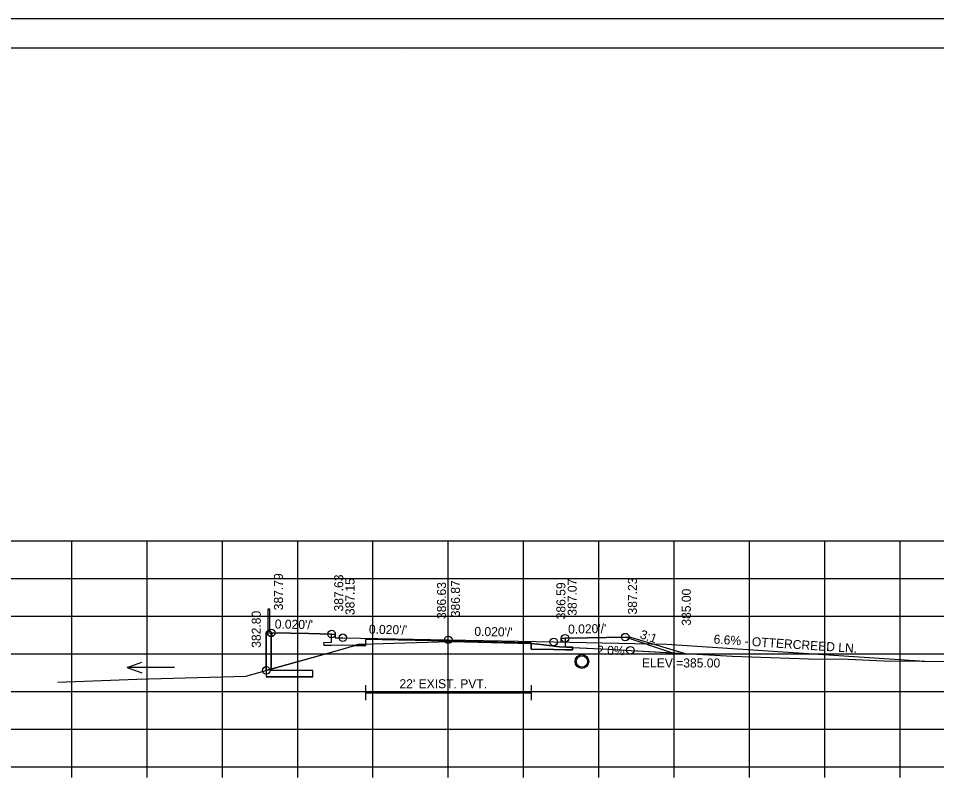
# Model space of a CAD drawing. Extents: x -37291014 to -37290680, y -936053 to -933067.
# Drawn here: x -37290900.2 to -37290778.3, y -933594.7 to -933493.3 of the extents above; entities that cross this region are included whole.
import ezdxf

# ---------------------------------------------------------------- set-up
doc = ezdxf.new("R2010")
doc.units = 0
for name, color, linetype in [('Default', 7, 'Continuous'), ('R_Alt Surface', 7, 'Continuous'), ('R_Axis', 7, 'Continuous'), ('R_Border', 7, 'Continuous'), ('R_Contours', 7, 'Continuous'), ('R_Drive', 7, 'Continuous'), ('R_Exist Surface', 7, 'Continuous'), ('R_Fin Surface', 7, 'Continuous'), ('R_Grid', 7, 'Continuous'), ('R_No Plot', 7, 'Continuous'), ('R_Water', 7, 'Continuous'), ('R_Water Annot', 7, 'Continuous'), ('R_Xsect Elev', 7, 'Continuous'), ('R_Xsect Slope', 7, 'Continuous')]:
    doc.layers.add(name, color=color, linetype=linetype)

msp = doc.modelspace()

# ---------------------------------------------------------------- linework, layer by layer
at = {"layer": 'Default'}
for p, q in [((-37290867.02, -933574.63), (-37290867.02, -933571.63)), ((-37290867.02, -933571.63), (-37290866.85, -933571.63)), ((-37290866.85, -933571.63), (-37290866.85, -933574.63)), ((-37290867.21, -933574.65), (-37290867.27, -933574.72)), ((-37290867.27, -933574.72), (-37290867.27, -933580.64)), ((-37290866.66, -933574.63), (-37290867.21, -933574.63)), ((-37290867.21, -933574.63), (-37290867.21, -933574.65)), ((-37290866.66, -933574.65), (-37290867.21, -933574.65)), ((-37290866.66, -933574.65), (-37290866.66, -933574.63)), ((-37290866.6, -933574.72), (-37290866.66, -933574.65)), ((-37290866.6, -933579.8), (-37290866.6, -933574.72)), ((-37290861.1, -933579.8), (-37290866.6, -933579.8)), ((-37290861.1, -933580.64), (-37290861.1, -933579.8)), ((-37290861.1, -933580.64), (-37290867.27, -933580.64))]:
    msp.add_line(p, q, dxfattribs=at)
msp.add_lwpolyline([(-37290866.52, -933575.32), (-37290866.6, -933575.32), (-37290866.6, -933574.82), (-37290866.52, -933574.82), (-37290866.52, -933575.32)], dxfattribs=at)
at = {"layer": 'R_Alt Surface'}
for points in [[(-37290827.6, -933575.54), (-37290827.6, -933576.63), (-37290826.59, -933576.65), (-37290826.6, -933577.07), (-37290827.6, -933577.05), (-37290829.1, -933577.02), (-37290832.1, -933576.96), (-37290832.1, -933576.13), (-37290843.1, -933575.91), (-37290854.1, -933575.69), (-37290854.1, -933576.52), (-37290857.1, -933576.46), (-37290858.6, -933576.49), (-37290859.6, -933576.51), (-37290859.61, -933576.09), (-37290858.6, -933576.07), (-37290858.6, -933574.98)], [(-37290854.1, -933581.77), (-37290854.1, -933583.77)], [(-37290854.1, -933582.77), (-37290832.1, -933582.77)], [(-37290832.1, -933581.77), (-37290832.1, -933583.77)]]:
    msp.add_lwpolyline(points, dxfattribs=at)
at = {"layer": 'R_Axis'}
for p, q in [((-37290993.1, -933592.61), (-37290693.1, -933592.61)), ((-37290893.1, -933594.01), (-37290893.1, -933592.61)), ((-37290883.1, -933594.01), (-37290883.1, -933592.61)), ((-37290873.1, -933594.01), (-37290873.1, -933592.61)), ((-37290863.1, -933594.01), (-37290863.1, -933592.61)), ((-37290853.1, -933594.01), (-37290853.1, -933592.61)), ((-37290843.1, -933594.01), (-37290843.1, -933592.61)), ((-37290833.1, -933594.01), (-37290833.1, -933592.61)), ((-37290823.1, -933594.01), (-37290823.1, -933592.61)), ((-37290813.1, -933594.01), (-37290813.1, -933592.61)), ((-37290803.1, -933594.01), (-37290803.1, -933592.61)), ((-37290793.1, -933594.01), (-37290793.1, -933592.61)), ((-37290783.1, -933594.01), (-37290783.1, -933592.61))]:
    msp.add_line(p, q, dxfattribs=at)
at = {"layer": 'R_Border'}
for p, q in [((-37291001.1, -933497.15), (-37290684.92, -933497.15)), ((-37290848.58, -933497.41), (-37290848.58, -933497.41)), ((-37290848.58, -933497.41), (-37290848.58, -933497.41))]:
    msp.add_line(p, q, dxfattribs=at)
at = {"layer": 'R_Contours'}
for p, q in [((-37290866.6, -933575.32), (-37290866.6, -933579.61)), ((-37290813.4, -933577.45), (-37290819.6, -933575.38)), ((-37290855.55, -933576.49), (-37290854.1, -933576.52)), ((-37290854.1, -933576.52), (-37290854.1, -933576.32)), ((-37290832.1, -933576.24), (-37290832.1, -933576.13)), ((-37290832.1, -933576.24), (-37290832.1, -933576.96)), ((-37290826.59, -933576.75), (-37290821.9, -933576.96)), ((-37290821.9, -933576.96), (-37290813.4, -933577.45)), ((-37290866.6, -933579.61), (-37290867.27, -933579.8)), ((-37290866.6, -933579.8), (-37290866.6, -933579.61)), ((-37290861.1, -933579.8), (-37290866.6, -933579.8)), ((-37290861.1, -933580.64), (-37290861.1, -933579.8)), ((-37290867.27, -933580.64), (-37290861.1, -933580.64))]:
    msp.add_line(p, q, dxfattribs=at)
for points in [[(-37290866.52, -933574.82), (-37290866.52, -933575.32), (-37290866.6, -933575.32)], [(-37290858.6, -933574.98), (-37290861.6, -933574.92), (-37290866.52, -933574.82)], [(-37290855.55, -933576.49), (-37290857.1, -933576.46), (-37290858.6, -933576.49), (-37290859.6, -933576.51), (-37290859.61, -933576.09), (-37290858.6, -933576.07), (-37290858.6, -933574.98)], [(-37290819.6, -933575.38), (-37290824.6, -933575.48), (-37290827.6, -933575.54)], [(-37290827.6, -933575.54), (-37290827.6, -933576.63), (-37290826.59, -933576.65), (-37290826.59, -933576.75)], [(-37290866.6, -933579.61), (-37290857.83, -933577.14), (-37290855.55, -933576.49)], [(-37290854.1, -933576.32), (-37290855.07, -933576.35), (-37290855.55, -933576.49)], [(-37290832.1, -933576.13), (-37290843.1, -933575.91), (-37290854.1, -933575.69), (-37290854.1, -933576.32)], [(-37290854.1, -933576.32), (-37290853.19, -933576.29), (-37290842.94, -933575.97), (-37290840.91, -933576.02), (-37290832.1, -933576.24)], [(-37290826.59, -933576.75), (-37290828.34, -933576.67), (-37290830.42, -933576.41), (-37290832.1, -933576.24)], [(-37290832.1, -933576.24), (-37290832.1, -933576.24)], [(-37290832.1, -933576.96), (-37290829.1, -933577.02), (-37290827.6, -933577.05), (-37290826.6, -933577.07), (-37290826.59, -933576.75)], [(-37290867.27, -933579.8), (-37290867.27, -933579.8), (-37290867.27, -933580.64)]]:
    msp.add_lwpolyline(points, dxfattribs=at)
at = {"layer": 'R_Drive'}
for p, q in [((-37290829.1, -933576.02), (-37290814.1, -933576.32)), ((-37290814.1, -933576.32), (-37290779.84, -933578.58))]:
    msp.add_line(p, q, dxfattribs=at)
at = {"layer": 'R_Exist Surface'}
msp.add_lwpolyline([(-37290894.96, -933581.34), (-37290884.45, -933580.97), (-37290869.97, -933580.56), (-37290857.83, -933577.14), (-37290855.07, -933576.35), (-37290853.19, -933576.29), (-37290842.94, -933575.97), (-37290840.91, -933576.02), (-37290832.1, -933576.24), (-37290830.42, -933576.41), (-37290828.34, -933576.67), (-37290821.9, -933576.96), (-37290805.37, -933577.91), (-37290795.28, -933578.26), (-37290790, -933578.32), (-37290785.24, -933578.53), (-37290770.21, -933578.67)], dxfattribs=at)
at = {"layer": 'R_Fin Surface'}
msp.add_lwpolyline([(-37290867.27, -933579.8), (-37290867.27, -933574.82), (-37290866.6, -933574.82), (-37290861.6, -933574.92), (-37290858.6, -933574.98), (-37290858.1, -933574.98), (-37290858.1, -933575.48), (-37290857.1, -933575.46), (-37290843.1, -933575.74), (-37290829.1, -933576.02), (-37290828.1, -933576.04), (-37290828.1, -933575.54), (-37290827.6, -933575.54), (-37290824.6, -933575.48), (-37290819.6, -933575.38), (-37290818.93, -933575.38), (-37290811.51, -933577.61)], dxfattribs=at)
at = {"layer": 'R_Grid'}
for p, q in [((-37290993.1, -933562.61), (-37290693.1, -933562.61)), ((-37290893.1, -933592.61), (-37290893.1, -933562.61)), ((-37290883.1, -933592.61), (-37290883.1, -933562.61)), ((-37290873.1, -933592.61), (-37290873.1, -933562.61)), ((-37290863.1, -933592.61), (-37290863.1, -933562.61)), ((-37290853.1, -933592.61), (-37290853.1, -933562.61)), ((-37290843.1, -933592.61), (-37290843.1, -933562.61)), ((-37290833.1, -933592.61), (-37290833.1, -933562.61)), ((-37290823.1, -933592.61), (-37290823.1, -933562.61)), ((-37290813.1, -933592.61), (-37290813.1, -933562.61)), ((-37290803.1, -933592.61), (-37290803.1, -933562.61)), ((-37290793.1, -933592.61), (-37290793.1, -933562.61)), ((-37290783.1, -933592.61), (-37290783.1, -933562.61)), ((-37290993.1, -933567.61), (-37290693.1, -933567.61)), ((-37290993.1, -933572.61), (-37290693.1, -933572.61)), ((-37290993.1, -933577.61), (-37290693.1, -933577.61)), ((-37290993.1, -933582.61), (-37290693.1, -933582.61)), ((-37290993.1, -933587.61), (-37290693.1, -933587.61)), ((-37290993.1, -933592.61), (-37290693.1, -933592.61))]:
    msp.add_line(p, q, dxfattribs=at)
at = {"layer": 'R_No Plot'}
msp.add_line((-37291013.5, -933493.25), (-37290680.17, -933493.25), dxfattribs=at)
for points in [[(-37291013.51, -933493.25), (-37290680.17, -933493.25), (-37290680.17, -933706.59), (-37291013.51, -933706.59)], [(-37290767.18, -933497.15), (-37290747.56, -933497.15), (-37290747.56, -933507.03), (-37290731.45, -933507.03), (-37290708.25, -933507.03), (-37290708.25, -933531.36), (-37290684.92, -933531.36), (-37290684.92, -933702.61), (-37291001.1, -933702.61), (-37291001.1, -933497.15)]]:
    msp.add_lwpolyline(points, close=True, dxfattribs=at)
for centre, radius in [((-37290866.6, -933574.82), 0.5), ((-37290858.6, -933574.98), 0.5), ((-37290857.1, -933575.46), 0.5), ((-37290843.1, -933575.74), 0.5), ((-37290829.1, -933576.02), 0.5), ((-37290827.6, -933575.54), 0.5), ((-37290819.6, -933575.38), 0.5), ((-37290818.93, -933577.13), 0.5), ((-37290825.36, -933578.62), 0.917), ((-37290867.27, -933579.8), 0.5)]:
    msp.add_circle(centre, radius, dxfattribs=at)
at = {"layer": 'R_Water'}
msp.add_circle((-37290825.36, -933578.62), 0.75, dxfattribs=at)
at = {"layer": 'R_Water Annot'}
for p, q in [((-37290885.72, -933579.42), (-37290883.8, -933578.72)), ((-37290879.44, -933579.42), (-37290885.72, -933579.42)), ((-37290885.72, -933579.42), (-37290883.8, -933580.12))]:
    msp.add_line(p, q, dxfattribs=at)
at = {"layer": 'R_Xsect Elev'}
msp.add_line((-37290843.1, -933575.98), (-37290843.1, -933565.98), dxfattribs=at)

# ---------------------------------------------------------------- texts
at = {"layer": 'R_Water'}
msp.add_text("22' EXIST. PVT.", height=1.2, dxfattribs=at).set_placement((-37290849.58, -933582.17))
at = {"layer": 'R_Xsect Elev'}
for s, rotation, p in [('387.79', 90, (-37290865.05, -933571.82)), ('387.63', 90, (-37290857.05, -933571.98)), ('387.15', 90, (-37290855.55, -933572.46)), ('386.63', 90, (-37290843.4, -933572.98)), ('386.87', 90, (-37290841.55, -933572.74)), ('386.59', 90, (-37290827.55, -933573.02)), ('387.07', 90, (-37290826.05, -933572.54)), ('387.23', 90, (-37290818.05, -933572.38)), ('385.00', 90, (-37290810.9, -933573.86)), ('382.80', 90, (-37290868, -933576.8)), ('6.6% - OTTERCREED LN.', 356.224, (-37290807.9, -933576.23)), ('2.0%', 358.8542, (-37290823.35, -933577.71))]:
    msp.add_text(s, height=1.2, rotation=rotation, dxfattribs=at).set_placement(p)
msp.add_text('ELEV.=385.00', height=1.2, dxfattribs=at).set_placement((-37290817.39, -933579.41))
at = {"layer": 'R_Xsect Slope'}
for s, rotation, p in [("0.020'/'", 358.8542, (-37290866.15, -933574.23)), ("0.020'/'", 358.8542, (-37290853.65, -933574.93)), ("0.020'/'", 358.8542, (-37290839.65, -933575.21)), ("0.020'/'", 1.1458, (-37290827.18, -933574.93)), ('3:1', 341.5668, (-37290817.74, -933575.51))]:
    msp.add_text(s, height=1.2, rotation=rotation, dxfattribs=at).set_placement(p)

doc.saveas('drawing.dxf')
